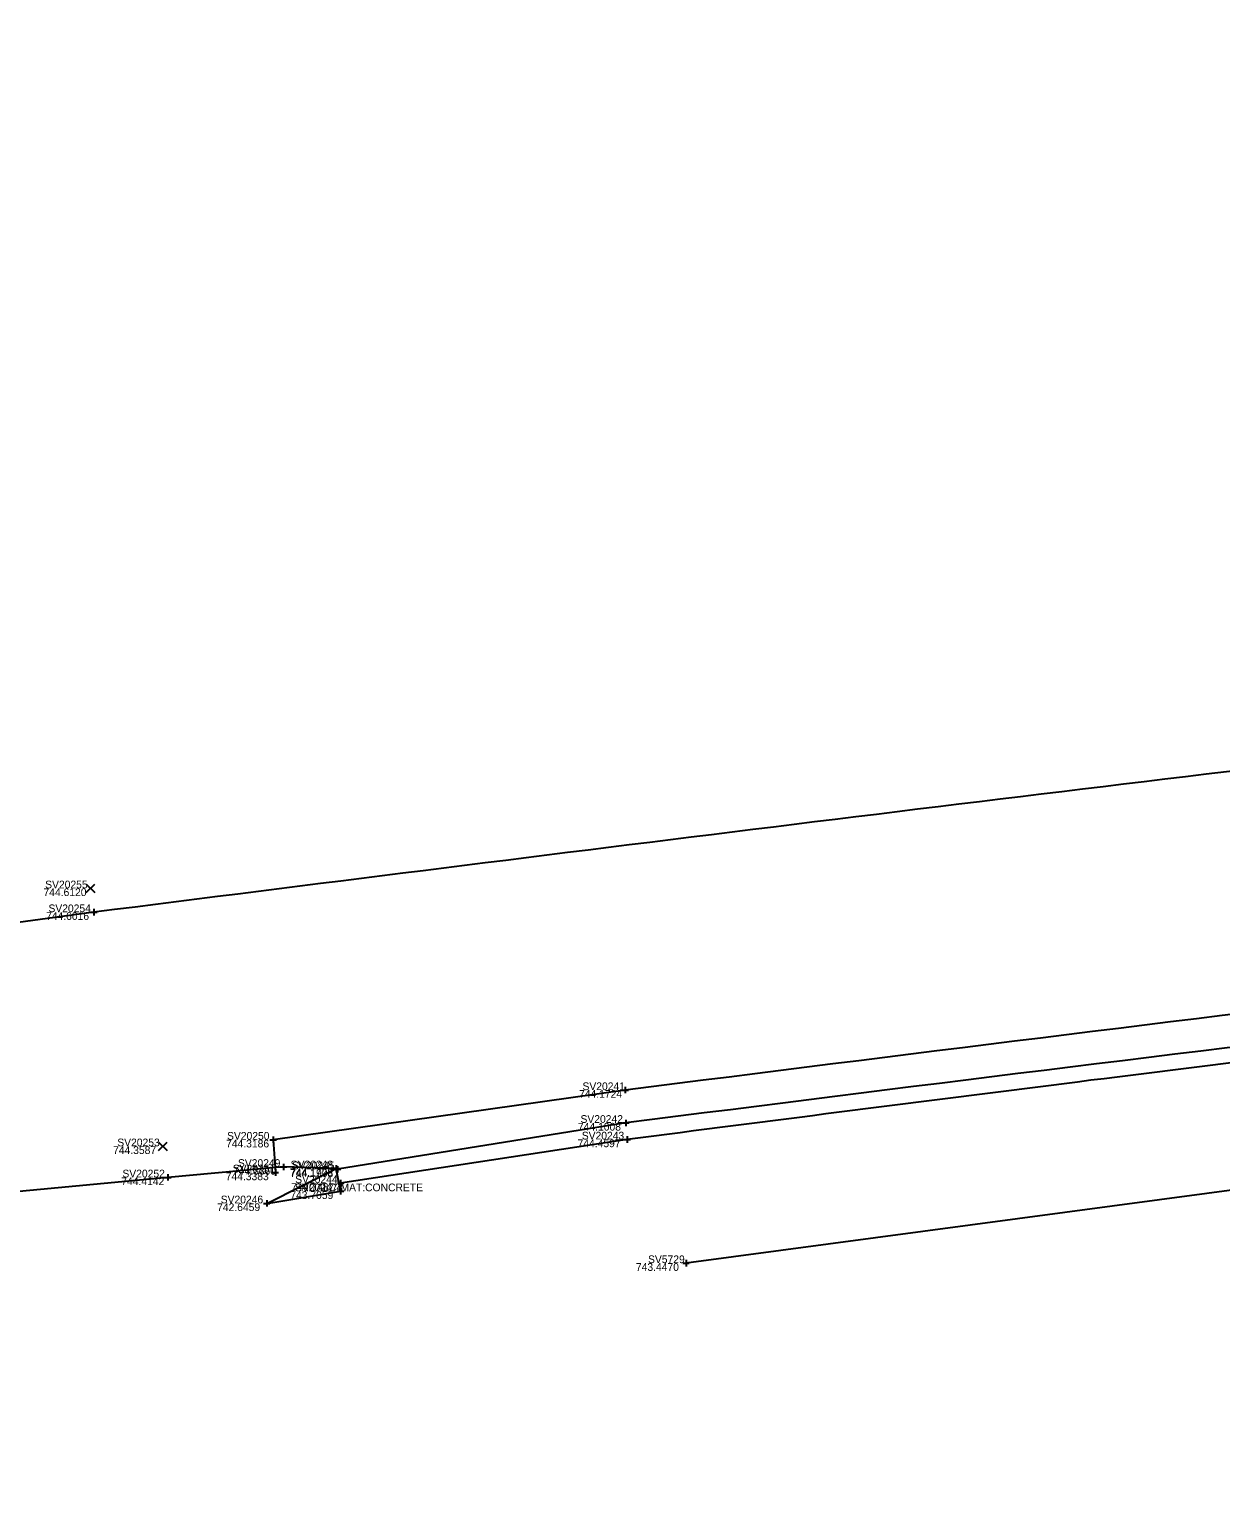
# Model space of a CAD drawing. Extents: x 182090 to 1832865, y 706265 to 714392.
# Drawn here: x 1826427.8 to 1826474.1, y 711769.5 to 711827.2 of the extents above; entities that cross this region are included whole.
import ezdxf

# ---------------------------------------------------------------- set-up
doc = ezdxf.new("R2010")
doc.units = 0
for name, color, linetype in [('PM_X_Surveyed_Line', 7, 'Continuous'), ('PV_X_Curb', 7, 'Continuous'), ('PV_X_EOP', 7, 'Continuous'), ('RD_X_Wall', 7, 'Continuous'), ('SV_X_Random_Point', 7, 'Continuous'), ('SV_X_Shot_Marker', 7, 'Continuous'), ('SV_X_Text_Description', 7, 'Continuous'), ('SV_X_Text_Elevation', 7, 'Continuous'), ('SV_X_Text_Name', 7, 'Continuous'), ('SV_X_Top_of_Bank', 7, 'Continuous')]:
    doc.layers.add(name, color=color, linetype=linetype)

msp = doc.modelspace()

# ---------------------------------------------------------------- linework, layer by layer
at = {"layer": 'PM_X_Surveyed_Line'}
msp.add_lwpolyline([(1826430.254, 711792.815), (1826381.163, 711786.114), (1826331.179, 711779.322)], dxfattribs=at)
msp.add_spline([(1827025.728, 711826.484), (1826983.074, 711826.96), (1826931.73, 711827.022), (1826881.921, 711826.242), (1826833.072, 711825.093), (1826780.428, 711823.259), (1826732.007, 711821.101), (1826680.858, 711817.898), (1826631.84, 711814.242), (1826581.049, 711809.676), (1826531.327, 711804.631), (1826481.541, 711799.131), (1826430.254, 711792.815)], degree=3, dxfattribs=at)
at = {"layer": 'PV_X_Curb'}
for p, q in [((1826450.953, 711784.617), (1826439.737, 711782.81)), ((1826451.006, 711783.971), (1826439.855, 711782.27))]:
    msp.add_line(p, q, dxfattribs=at)
for points in [[(1826901.912, 711815.3), (1826882.173, 711815.097), (1826832.36, 711813.949), (1826782.297, 711812.096), (1826732.314, 711809.562), (1826726.133, 711809.26), (1826716.215, 711808.772), (1826714.807, 711808.749), (1826682.28, 711806.771), (1826632.361, 711803.137), (1826581.609, 711798.783), (1826532.411, 711793.822), (1826483.502, 711788.619), (1826450.953, 711784.617)], [(1826714.94, 711807.86), (1826681.911, 711806.067), (1826631.881, 711802.483), (1826581.589, 711798.22), (1826532.14, 711793.401), (1826483.991, 711788.113), (1826451.006, 711783.971)]]:
    msp.add_spline(points, degree=3, dxfattribs=at)
at = {"layer": 'PV_X_EOP'}
msp.add_lwpolyline([(1826450.925, 711785.892), (1826437.23, 711783.962), (1826437.319, 711782.687)], dxfattribs=at)
msp.add_spline([(1826901.825, 711816.294), (1826882.118, 711816.436), (1826832.241, 711815.145), (1826782.308, 711813.42), (1826732.395, 711810.782), (1826715.181, 711809.953), (1826682.256, 711807.982), (1826632.26, 711804.349), (1826581.328, 711799.953), (1826532.507, 711795.251), (1826483.251, 711789.886), (1826450.925, 711785.892)], degree=3, dxfattribs=at)
at = {"layer": 'RD_X_Wall'}
for points in [[(1826436.979, 711781.485), (1826439.85, 711781.956), (1826439.683, 711782.847), (1826437.632, 711782.904), (1826433.132, 711782.495), (1826425.271, 711781.753), (1826424.807, 711781.8), (1826383.31, 711776.252), (1826333.292, 711769.539)], [(1826436.979, 711781.485), (1826439.683, 711782.847), (1826437.632, 711782.904), (1826433.132, 711782.495), (1826425.271, 711781.753), (1826424.807, 711781.8), (1826383.31, 711776.252)], [(1826436.979, 711781.485), (1826439.683, 711782.847), (1826437.632, 711782.904), (1826433.132, 711782.495), (1826425.271, 711781.753), (1826424.807, 711781.8), (1826383.31, 711776.252)], [(1826436.979, 711781.485), (1826439.683, 711782.847), (1826437.632, 711782.904), (1826433.132, 711782.495), (1826425.271, 711781.753), (1826424.807, 711781.8), (1826383.31, 711776.252)]]:
    msp.add_lwpolyline(points, dxfattribs=at)
at = {"layer": 'SV_X_Random_Point'}
for p, q in [((1826429.962, 711793.576), (1826430.296, 711793.91)), ((1826429.962, 711793.91), (1826430.296, 711793.576)), ((1826432.767, 711783.539), (1826433.101, 711783.873)), ((1826432.767, 711783.873), (1826433.101, 711783.539))]:
    msp.add_line(p, q, dxfattribs=at)
at = {"layer": 'SV_X_Shot_Marker'}
for p, q in [((1826430.254, 711792.94), (1826430.254, 711792.69)), ((1826430.129, 711792.815), (1826430.379, 711792.815)), ((1826430.254, 711792.815), (1826430.254, 711792.815)), ((1826450.925, 711786.017), (1826450.925, 711785.767)), ((1826450.8, 711785.892), (1826451.05, 711785.892)), ((1826450.925, 711785.892), (1826450.925, 711785.892)), ((1826450.828, 711784.617), (1826451.078, 711784.617)), ((1826450.953, 711784.742), (1826450.953, 711784.492)), ((1826450.953, 711784.617), (1826450.953, 711784.617)), ((1826437.105, 711783.962), (1826437.355, 711783.962)), ((1826437.23, 711784.087), (1826437.23, 711783.837)), ((1826437.23, 711783.962), (1826437.23, 711783.962)), ((1826450.881, 711783.971), (1826451.131, 711783.971)), ((1826451.006, 711784.096), (1826451.006, 711783.846)), ((1826451.006, 711783.971), (1826451.006, 711783.971)), ((1826433.132, 711782.62), (1826433.132, 711782.37)), ((1826437.194, 711782.687), (1826437.444, 711782.687)), ((1826437.319, 711782.812), (1826437.319, 711782.562)), ((1826437.319, 711782.687), (1826437.319, 711782.687)), ((1826437.507, 711782.904), (1826437.757, 711782.904)), ((1826437.632, 711783.029), (1826437.632, 711782.779)), ((1826437.632, 711782.904), (1826437.632, 711782.904)), ((1826439.558, 711782.847), (1826439.808, 711782.847)), ((1826439.612, 711782.81), (1826439.862, 711782.81)), ((1826439.683, 711782.972), (1826439.683, 711782.722)), ((1826439.683, 711782.847), (1826439.683, 711782.847)), ((1826439.737, 711782.935), (1826439.737, 711782.685)), ((1826439.737, 711782.81), (1826439.737, 711782.81)), ((1826433.007, 711782.495), (1826433.257, 711782.495)), ((1826433.132, 711782.495), (1826433.132, 711782.495)), ((1826439.725, 711781.956), (1826439.975, 711781.956)), ((1826439.725, 711781.956), (1826439.975, 711781.956)), ((1826439.73, 711782.27), (1826439.98, 711782.27)), ((1826439.85, 711782.081), (1826439.85, 711781.831)), ((1826439.85, 711782.081), (1826439.85, 711781.831)), ((1826439.85, 711781.956), (1826439.85, 711781.956)), ((1826439.85, 711781.956), (1826439.85, 711781.956)), ((1826439.855, 711782.395), (1826439.855, 711782.145)), ((1826439.855, 711782.27), (1826439.855, 711782.27)), ((1826436.854, 711781.485), (1826437.104, 711781.485)), ((1826436.979, 711781.61), (1826436.979, 711781.36)), ((1826436.979, 711781.485), (1826436.979, 711781.485)), ((1826453.171, 711779.159), (1826453.421, 711779.159)), ((1826453.296, 711779.284), (1826453.296, 711779.034)), ((1826453.296, 711779.159), (1826453.296, 711779.159))]:
    msp.add_line(p, q, dxfattribs=at)
at = {"layer": 'SV_X_Top_of_Bank'}
msp.add_lwpolyline([(1827026.368, 711816.963), (1827006.929, 711815.475), (1826980.673, 711814.351), (1826951.231, 711812.986), (1826926.218, 711811.851), (1826900.22, 711811.648), (1826852.566, 711810.339), (1826818.963, 711809.177), (1826790.218, 711808.203), (1826762.005, 711807.349), (1826728.674, 711804.562), (1826690.326, 711803.204), (1826661.121, 711801.736), (1826628.134, 711798.954), (1826606.462, 711796.407), (1826570.536, 711793.444), (1826537.465, 711789.948), (1826509.361, 711786.66), (1826453.296, 711779.159)], dxfattribs=at)

# ---------------------------------------------------------------- texts
at = {"layer": 'SV_X_Text_Description'}
msp.add_text('MAT:CONCRETE', height=0.3, dxfattribs=at).set_placement((1826439.85, 711781.956))
at = {"layer": 'SV_X_Text_Elevation'}
for s, p in [('744.6120', (1826428.296, 711793.443)), ('744.6016', (1826428.395, 711792.515)), ('744.1724', (1826449.13, 711785.593)), ('744.1008', (1826449.088, 711784.317)), ('744.3587', (1826431.004, 711783.406)), ('744.3186', (1826435.4, 711783.662)), ('744.4597', (1826449.074, 711783.671)), ('744.3383', (1826435.385, 711782.387)), ('744.3360', (1826435.667, 711782.604)), ('744.1728', (1826437.884, 711782.547)), ('744.1908', (1826437.895, 711782.51)), ('744.4142', (1826431.322, 711782.195)), ('743.7059', (1826437.897, 711781.656)), ('743.7059', (1826437.897, 711781.656)), ('744.7487', (1826437.932, 711781.97)), ('742.6459', (1826435.051, 711781.186)), ('743.4470', (1826451.343, 711778.859))]:
    msp.add_text(s, height=0.3, dxfattribs=at).set_placement(p)
at = {"layer": 'SV_X_Text_Name'}
for s, p in [('SV20255', (1826428.362, 711793.743)), ('SV20254', (1826428.489, 711792.815)), ('SV20241', (1826449.265, 711785.892)), ('SV20242', (1826449.187, 711784.617)), ('SV20250', (1826435.437, 711783.962)), ('SV20243', (1826449.237, 711783.971)), ('SV20253', (1826431.167, 711783.706)), ('SV20249', (1826435.861, 711782.904)), ('SV20248', (1826437.912, 711782.847)), ('SV20245', (1826437.968, 711782.81)), ('SV20252', (1826431.367, 711782.495)), ('SV20251', (1826435.662, 711782.687)), ('SV20244', (1826438.088, 711782.27)), ('SV20247', (1826438.081, 711781.956)), ('NCALC4', (1826438.331, 711781.956)), ('SV20246', (1826435.191, 711781.485)), ('SV5729', (1826451.815, 711779.159))]:
    msp.add_text(s, height=0.3, dxfattribs=at).set_placement(p)

doc.saveas('drawing.dxf')
